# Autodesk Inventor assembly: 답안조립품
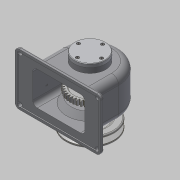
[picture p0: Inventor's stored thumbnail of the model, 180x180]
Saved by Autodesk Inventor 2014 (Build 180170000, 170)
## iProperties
Created: 2016-01
Part Number: 답안조립품
Document SubType Name: Assembly
Designer: basic
Author: basic
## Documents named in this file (16)
- C:\Users\basic\Desktop\460106V1010\답안조립품.iam
- C:\Users\basic\Desktop\460106V1010\본체.ipt
- C:\Users\basic\Desktop\460106V1010\V-벨트풀리.ipt
- C:\Users\basic\Desktop\460106V1010\뒤커버.ipt
- C:\Users\basic\Desktop\460106V1010\멈춤나사 - M4x10.ipt
- C:\Users\basic\Desktop\460106V1010\베어링 6203.ipt
- C:\Users\basic\Desktop\460106V1010\볼트 M3 x 8.ipt
- C:\Users\basic\Desktop\460106V1010\볼트 M3 x 10.ipt
- C:\Users\basic\Desktop\460106V1010\부시1.ipt
- C:\Users\basic\Desktop\460106V1010\부시2.ipt
- C:\Users\basic\Desktop\460106V1010\스퍼기어.ipt
- C:\Users\basic\Desktop\460106V1010\앞커버.ipt
- C:\Users\basic\Desktop\460106V1010\오일씰 28 40 8.ipt
- C:\Users\basic\Desktop\460106V1010\축.ipt
- C:\Users\basic\Desktop\460106V1010\키 - 5 x 5 x 18.ipt
- C:\Users\basic\Desktop\460106V1010\키 - 6 x 6 x 22.ipt
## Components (9 placed, 3 different names)
1. V-벨트풀리:1 — 각도:2
2. ISO 4762 M3 x 10:1
3. ISO 4762 M3 x 8:1
4. ISO 4762 M3 x 10:2
5. ISO 4762 M3 x 8:2
6. ISO 4762 M3 x 10:3
7. ISO 4762 M3 x 8:3
8. ISO 4762 M3 x 10:4
9. ISO 4762 M3 x 8:4
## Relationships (1: Angle 1)
- 각도:2 [Angle]: V-벨트풀리:1
